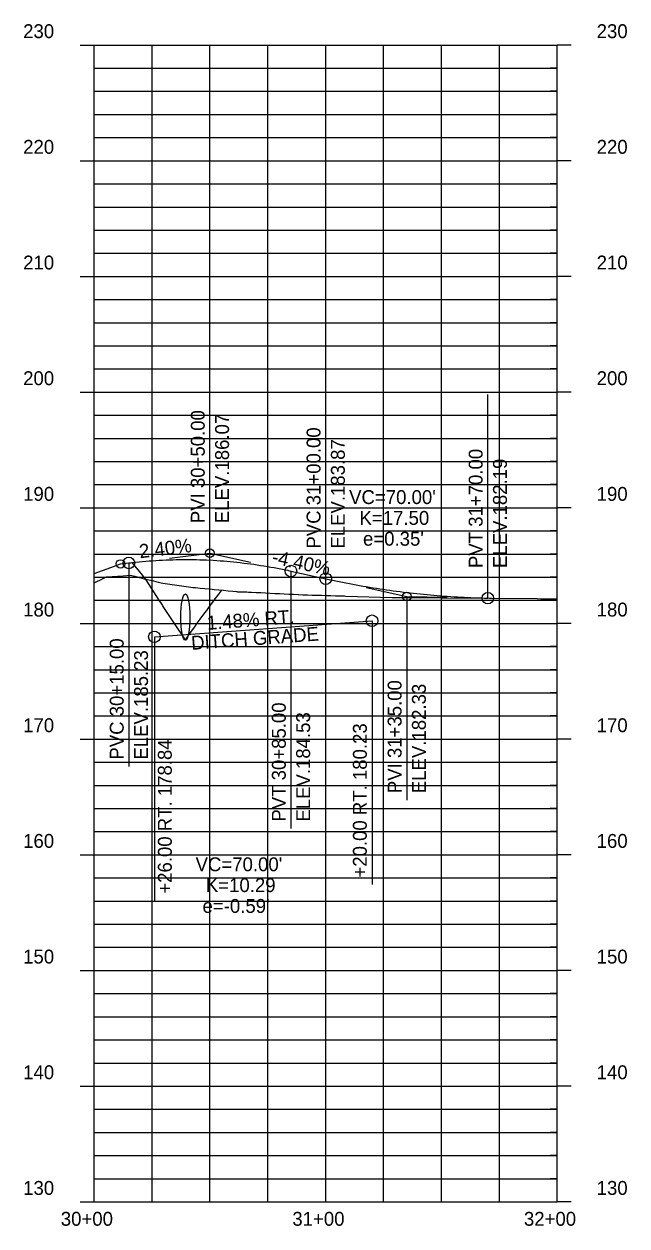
# Model space of a CAD drawing. Extents: x 1409239 to 1412142, y 1838831 to 1842626.
# Drawn here: x 1410908 to 1411168, y 1840947 to 1841467 of the extents above; entities that cross this region are included whole.
import ezdxf

# ---------------------------------------------------------------- set-up
doc = ezdxf.new("R2010")
doc.units = 0
for name, color, linetype in [('63', 7, 'Continuous'), ('R_Axis_Annotation', 7, 'Continuous'), ('R_Drainage', 7, 'Continuous'), ('R_Exist Surface', 7, 'Continuous'), ('R_Grid', 7, 'Continuous'), ('R_Grid Annot', 7, 'Continuous'), ('R_Grid_Minor', 7, 'Continuous'), ('R_Prop Surface', 7, 'Continuous'), ('R_Vert Alg', 7, 'Continuous'), ('R_Vert Alg Annot', 7, 'Continuous')]:
    doc.layers.add(name, color=color, linetype=linetype)

msp = doc.modelspace()

# ---------------------------------------------------------------- linework, layer by layer
at = {"layer": 'R_Drainage'}
msp.add_ellipse((1410977.35, 1841210.43), major_axis=(0, 10), ratio=0.2, dxfattribs=at)
at = {"layer": 'R_Exist Surface'}
msp.add_lwpolyline([(1410937.97, 1841225.2), (1410941.93, 1841227.07), (1410943.27, 1841227.75), (1410950.48, 1841228.29), (1410953.54, 1841228.59), (1410955.53, 1841228.06), (1410957.55, 1841227.52), (1410959.56, 1841226.98), (1410960.12, 1841226.84), (1410961.58, 1841226.5), (1410963.6, 1841226.04), (1410965.61, 1841225.57), (1410967.61, 1841225.11), (1410967.63, 1841225.11), (1410969.65, 1841224.81), (1410971.66, 1841224.52), (1410973.68, 1841224.23), (1410975.7, 1841223.94), (1410977.71, 1841223.66), (1410979.73, 1841223.38), (1410980.6, 1841223.26), (1410981.74, 1841223.15), (1410983.76, 1841222.97), (1410985.78, 1841222.79), (1410987.79, 1841222.62), (1410988.14, 1841222.59), (1410989.81, 1841222.41), (1410991.83, 1841222.19), (1410993.84, 1841221.98), (1410995.86, 1841221.77), (1410997.87, 1841221.57), (1410999.49, 1841221.41), (1410999.53, 1841221.41), (1410999.89, 1841221.4), (1411001.91, 1841221.34), (1411003.92, 1841221.27), (1411004.58, 1841221.25), (1411005.94, 1841221.19), (1411007.96, 1841221.09), (1411009.97, 1841220.99), (1411011.99, 1841220.88), (1411014.01, 1841220.78), (1411016.02, 1841220.67), (1411017.58, 1841220.58), (1411018.04, 1841220.56), (1411020.05, 1841220.46), (1411022.07, 1841220.36), (1411024.09, 1841220.26), (1411026.1, 1841220.16), (1411026.21, 1841220.16), (1411028.12, 1841220.03), (1411028.5, 1841220.01), (1411030.14, 1841219.97), (1411032.15, 1841219.92), (1411034.17, 1841219.88), (1411036.18, 1841219.82), (1411038.2, 1841219.77), (1411040.22, 1841219.71), (1411042.23, 1841219.65), (1411046.04, 1841219.54), (1411046.62, 1841219.52), (1411066.65, 1841218.92), (1411067.19, 1841218.91), (1411080.39, 1841218.83), (1411087.99, 1841218.76), (1411088.29, 1841218.76), (1411108.76, 1841218.58), (1411109.9, 1841218.55), (1411129.35, 1841218.38), (1411130.93, 1841218.35), (1411137.97, 1841218.29)], dxfattribs=at)
at = {"layer": 'R_Grid'}
for p, q in [((1410937.97, 1840957.67), (1410937.97, 1841457.67)), ((1410937.97, 1841457.67), (1411137.97, 1841457.67)), ((1410937.97, 1841457.67), (1411137.97, 1841457.67)), ((1411037.97, 1840957.67), (1411037.97, 1841457.67)), ((1411137.97, 1840957.67), (1411137.97, 1841457.67)), ((1410937.97, 1841407.67), (1411137.97, 1841407.67)), ((1410937.97, 1841357.67), (1411137.97, 1841357.67)), ((1410937.97, 1841307.67), (1411137.97, 1841307.67)), ((1410937.97, 1841257.67), (1411137.97, 1841257.67)), ((1410937.97, 1841207.67), (1411137.97, 1841207.67)), ((1410937.97, 1841157.67), (1411137.97, 1841157.67)), ((1410937.97, 1841107.67), (1411137.97, 1841107.67)), ((1410937.97, 1841057.67), (1411137.97, 1841057.67)), ((1410937.97, 1841007.67), (1411137.97, 1841007.67)), ((1410937.97, 1840957.67), (1411137.97, 1840957.67))]:
    msp.add_line(p, q, dxfattribs=at)
at = {"layer": 'R_Grid Annot'}
for p, q in [((1410931.97, 1841457.67), (1410937.97, 1841457.67)), ((1410931.97, 1841457.67), (1410937.97, 1841457.67)), ((1411143.97, 1841457.67), (1411137.97, 1841457.67)), ((1411143.97, 1841457.67), (1411137.97, 1841457.67)), ((1410937.97, 1841447.67), (1410940.97, 1841447.67)), ((1411137.97, 1841447.67), (1411134.97, 1841447.67)), ((1410937.97, 1841437.67), (1410940.97, 1841437.67)), ((1411137.97, 1841437.67), (1411134.97, 1841437.67)), ((1410937.97, 1841427.67), (1410940.97, 1841427.67)), ((1411137.97, 1841427.67), (1411134.97, 1841427.67)), ((1410937.97, 1841417.67), (1410940.97, 1841417.67)), ((1411137.97, 1841417.67), (1411134.97, 1841417.67)), ((1410931.97, 1841407.67), (1410937.97, 1841407.67)), ((1411143.97, 1841407.67), (1411137.97, 1841407.67)), ((1410937.97, 1841397.67), (1410940.97, 1841397.67)), ((1411137.97, 1841397.67), (1411134.97, 1841397.67)), ((1410937.97, 1841387.67), (1410940.97, 1841387.67)), ((1411137.97, 1841387.67), (1411134.97, 1841387.67)), ((1410937.97, 1841377.67), (1410940.97, 1841377.67)), ((1411137.97, 1841377.67), (1411134.97, 1841377.67)), ((1410937.97, 1841367.67), (1410940.97, 1841367.67)), ((1411137.97, 1841367.67), (1411134.97, 1841367.67)), ((1410931.97, 1841357.67), (1410937.97, 1841357.67)), ((1411143.97, 1841357.67), (1411137.97, 1841357.67)), ((1410937.97, 1841347.67), (1410940.97, 1841347.67)), ((1411137.97, 1841347.67), (1411134.97, 1841347.67)), ((1410937.97, 1841337.67), (1410940.97, 1841337.67)), ((1411137.97, 1841337.67), (1411134.97, 1841337.67)), ((1410937.97, 1841327.67), (1410940.97, 1841327.67)), ((1411137.97, 1841327.67), (1411134.97, 1841327.67)), ((1410937.97, 1841317.67), (1410940.97, 1841317.67)), ((1411137.97, 1841317.67), (1411134.97, 1841317.67)), ((1410931.97, 1841307.67), (1410937.97, 1841307.67)), ((1411143.97, 1841307.67), (1411137.97, 1841307.67)), ((1410937.97, 1841297.67), (1410940.97, 1841297.67)), ((1411137.97, 1841297.67), (1411134.97, 1841297.67)), ((1410937.97, 1841287.67), (1410940.97, 1841287.67)), ((1411137.97, 1841287.67), (1411134.97, 1841287.67)), ((1410937.97, 1841277.67), (1410940.97, 1841277.67)), ((1411137.97, 1841277.67), (1411134.97, 1841277.67)), ((1410937.97, 1841267.67), (1410940.97, 1841267.67)), ((1411137.97, 1841267.67), (1411134.97, 1841267.67)), ((1410931.97, 1841257.67), (1410937.97, 1841257.67)), ((1411143.97, 1841257.67), (1411137.97, 1841257.67)), ((1410937.97, 1841247.67), (1410940.97, 1841247.67)), ((1411137.97, 1841247.67), (1411134.97, 1841247.67)), ((1410937.97, 1841237.67), (1410940.97, 1841237.67)), ((1411137.97, 1841237.67), (1411134.97, 1841237.67)), ((1410937.97, 1841227.67), (1410940.97, 1841227.67)), ((1411137.97, 1841227.67), (1411134.97, 1841227.67)), ((1410937.97, 1841217.67), (1410940.97, 1841217.67)), ((1411137.97, 1841217.67), (1411134.97, 1841217.67)), ((1410931.97, 1841207.67), (1410937.97, 1841207.67)), ((1411143.97, 1841207.67), (1411137.97, 1841207.67)), ((1410937.97, 1841197.67), (1410940.97, 1841197.67)), ((1411137.97, 1841197.67), (1411134.97, 1841197.67)), ((1410937.97, 1841187.67), (1410940.97, 1841187.67)), ((1411137.97, 1841187.67), (1411134.97, 1841187.67)), ((1410937.97, 1841177.67), (1410940.97, 1841177.67)), ((1411137.97, 1841177.67), (1411134.97, 1841177.67)), ((1410937.97, 1841167.67), (1410940.97, 1841167.67)), ((1411137.97, 1841167.67), (1411134.97, 1841167.67)), ((1410931.97, 1841157.67), (1410937.97, 1841157.67)), ((1411143.97, 1841157.67), (1411137.97, 1841157.67)), ((1410937.97, 1841147.67), (1410940.97, 1841147.67)), ((1411137.97, 1841147.67), (1411134.97, 1841147.67)), ((1410937.97, 1841137.67), (1410940.97, 1841137.67)), ((1411137.97, 1841137.67), (1411134.97, 1841137.67)), ((1410937.97, 1841127.67), (1410940.97, 1841127.67)), ((1411137.97, 1841127.67), (1411134.97, 1841127.67)), ((1410937.97, 1841117.67), (1410940.97, 1841117.67)), ((1411137.97, 1841117.67), (1411134.97, 1841117.67)), ((1410931.97, 1841107.67), (1410937.97, 1841107.67)), ((1411143.97, 1841107.67), (1411137.97, 1841107.67)), ((1410937.97, 1841097.67), (1410940.97, 1841097.67)), ((1411137.97, 1841097.67), (1411134.97, 1841097.67)), ((1410937.97, 1841087.67), (1410940.97, 1841087.67)), ((1411137.97, 1841087.67), (1411134.97, 1841087.67)), ((1410937.97, 1841077.67), (1410940.97, 1841077.67)), ((1411137.97, 1841077.67), (1411134.97, 1841077.67)), ((1410937.97, 1841067.67), (1410940.97, 1841067.67)), ((1411137.97, 1841067.67), (1411134.97, 1841067.67)), ((1410931.97, 1841057.67), (1410937.97, 1841057.67)), ((1411143.97, 1841057.67), (1411137.97, 1841057.67)), ((1410937.97, 1841047.67), (1410940.97, 1841047.67)), ((1411137.97, 1841047.67), (1411134.97, 1841047.67)), ((1410937.97, 1841037.67), (1410940.97, 1841037.67)), ((1411137.97, 1841037.67), (1411134.97, 1841037.67)), ((1410937.97, 1841027.67), (1410940.97, 1841027.67)), ((1411137.97, 1841027.67), (1411134.97, 1841027.67)), ((1410937.97, 1841017.67), (1410940.97, 1841017.67)), ((1411137.97, 1841017.67), (1411134.97, 1841017.67)), ((1410931.97, 1841007.67), (1410937.97, 1841007.67)), ((1411143.97, 1841007.67), (1411137.97, 1841007.67)), ((1410937.97, 1840997.67), (1410940.97, 1840997.67)), ((1411137.97, 1840997.67), (1411134.97, 1840997.67)), ((1410937.97, 1840987.67), (1410940.97, 1840987.67)), ((1411137.97, 1840987.67), (1411134.97, 1840987.67)), ((1410937.97, 1840977.67), (1410940.97, 1840977.67)), ((1411137.97, 1840977.67), (1411134.97, 1840977.67)), ((1410937.97, 1840967.67), (1410940.97, 1840967.67)), ((1411137.97, 1840967.67), (1411134.97, 1840967.67)), ((1410931.97, 1840957.67), (1410937.97, 1840957.67)), ((1411143.97, 1840957.67), (1411137.97, 1840957.67))]:
    msp.add_line(p, q, dxfattribs=at)
at = {"layer": 'R_Grid_Minor'}
for p, q in [((1410962.97, 1840957.67), (1410962.97, 1841457.67)), ((1410987.97, 1840957.67), (1410987.97, 1841457.67)), ((1411012.97, 1840957.67), (1411012.97, 1841457.67)), ((1411062.97, 1840957.67), (1411062.97, 1841457.67)), ((1411087.97, 1840957.67), (1411087.97, 1841457.67)), ((1411112.97, 1840957.67), (1411112.97, 1841457.67)), ((1410937.97, 1841447.67), (1411137.97, 1841447.67)), ((1410937.97, 1841437.67), (1411137.97, 1841437.67)), ((1410937.97, 1841427.67), (1411137.97, 1841427.67)), ((1410937.97, 1841417.67), (1411137.97, 1841417.67)), ((1410937.97, 1841397.67), (1411137.97, 1841397.67)), ((1410937.97, 1841387.67), (1411137.97, 1841387.67)), ((1410937.97, 1841377.67), (1411137.97, 1841377.67)), ((1410937.97, 1841367.67), (1411137.97, 1841367.67)), ((1410937.97, 1841347.67), (1411137.97, 1841347.67)), ((1410937.97, 1841337.67), (1411137.97, 1841337.67)), ((1410937.97, 1841327.67), (1411137.97, 1841327.67)), ((1410937.97, 1841317.67), (1411137.97, 1841317.67)), ((1410937.97, 1841297.67), (1411137.97, 1841297.67)), ((1410937.97, 1841287.67), (1411137.97, 1841287.67)), ((1410937.97, 1841277.67), (1411137.97, 1841277.67)), ((1410937.97, 1841267.67), (1411137.97, 1841267.67)), ((1410937.97, 1841247.67), (1411137.97, 1841247.67)), ((1410937.97, 1841237.67), (1411137.97, 1841237.67)), ((1410937.97, 1841227.67), (1411137.97, 1841227.67)), ((1410937.97, 1841217.67), (1411137.97, 1841217.67)), ((1410937.97, 1841197.67), (1411137.97, 1841197.67)), ((1410937.97, 1841187.67), (1411137.97, 1841187.67)), ((1410937.97, 1841177.67), (1411137.97, 1841177.67)), ((1410937.97, 1841167.67), (1411137.97, 1841167.67)), ((1410937.97, 1841147.67), (1411137.97, 1841147.67)), ((1410937.97, 1841137.67), (1411137.97, 1841137.67)), ((1410937.97, 1841127.67), (1411137.97, 1841127.67)), ((1410937.97, 1841117.67), (1411137.97, 1841117.67)), ((1410937.97, 1841097.67), (1411137.97, 1841097.67)), ((1410937.97, 1841087.67), (1411137.97, 1841087.67)), ((1410937.97, 1841077.67), (1411137.97, 1841077.67)), ((1410937.97, 1841067.67), (1411137.97, 1841067.67)), ((1410937.97, 1841047.67), (1411137.97, 1841047.67)), ((1410937.97, 1841037.67), (1411137.97, 1841037.67)), ((1410937.97, 1841027.67), (1411137.97, 1841027.67)), ((1410937.97, 1841017.67), (1411137.97, 1841017.67)), ((1410937.97, 1840997.67), (1411137.97, 1840997.67)), ((1410937.97, 1840987.67), (1411137.97, 1840987.67)), ((1410937.97, 1840977.67), (1411137.97, 1840977.67)), ((1410937.97, 1840967.67), (1411137.97, 1840967.67))]:
    msp.add_line(p, q, dxfattribs=at)
at = {"layer": 'R_Prop Surface'}
for points in [[(1410937.97, 1841229.32), (1410945.12, 1841231.88), (1410949.33, 1841233.37), (1410952.97, 1841233.81), (1410953.7, 1841233.9)], [(1410953.7, 1841233.9), (1410954.21, 1841233.96), (1410955.53, 1841232.38), (1410957.55, 1841229.98), (1410958.27, 1841229.13), (1410959.34, 1841227.86), (1410959.56, 1841227.59), (1410959.68, 1841227.45), (1410961.58, 1841224.46), (1410963.6, 1841221.3), (1410965.61, 1841218.17), (1410967.43, 1841215.37), (1410967.63, 1841215.06), (1410969.65, 1841211.98), (1410971.66, 1841208.92), (1410973.68, 1841205.89), (1410974.24, 1841205.06), (1410975.5, 1841203.18), (1410975.7, 1841202.88), (1410977.35, 1841200.43), (1410977.71, 1841200.96), (1410979.73, 1841203.83), (1410981.74, 1841206.67), (1410982.51, 1841207.74), (1410983.76, 1841209.47), (1410985.78, 1841212.25), (1410986.58, 1841213.33), (1410987.79, 1841214.99), (1410989.16, 1841216.82), (1410989.81, 1841217.7), (1410991.83, 1841220.38), (1410993.11, 1841222.06)]]:
    msp.add_lwpolyline(points, dxfattribs=at)
at = {"layer": 'R_Vert Alg'}
for p, q in [((1410949.35, 1841233.38), (1410952.97, 1841233.81)), ((1411022.97, 1841230.31), (1411037.97, 1841227.01)), ((1410963.97, 1841201.86), (1411057.97, 1841208.82))]:
    msp.add_line(p, q, dxfattribs=at)
for points in [[(1410952.97, 1841233.81), (1410954.43, 1841233.98), (1410955.89, 1841234.14), (1410957.34, 1841234.29), (1410958.8, 1841234.43), (1410960.26, 1841234.56), (1410961.72, 1841234.68), (1410963.18, 1841234.78), (1410964.64, 1841234.88), (1410966.09, 1841234.97), (1410967.55, 1841235.05), (1410969.01, 1841235.11), (1410970.47, 1841235.17), (1410971.93, 1841235.21), (1410973.39, 1841235.25), (1410974.84, 1841235.27), (1410976.3, 1841235.29), (1410977.76, 1841235.29), (1410979.22, 1841235.29), (1410980.68, 1841235.27), (1410982.14, 1841235.25), (1410983.59, 1841235.21), (1410985.05, 1841235.16), (1410986.51, 1841235.1), (1410989.43, 1841234.96), (1410990.89, 1841234.87), (1410992.34, 1841234.77), (1410993.8, 1841234.66), (1410995.26, 1841234.54), (1410996.72, 1841234.41), (1410998.18, 1841234.27), (1410999.64, 1841234.12), (1411001.09, 1841233.96), (1411002.55, 1841233.79), (1411004.01, 1841233.61), (1411005.47, 1841233.42), (1411006.93, 1841233.22), (1411008.39, 1841233), (1411009.84, 1841232.78), (1411011.3, 1841232.55), (1411012.76, 1841232.3), (1411014.22, 1841232.05), (1411015.68, 1841231.79), (1411017.14, 1841231.51), (1411018.59, 1841231.23), (1411020.05, 1841230.93), (1411021.51, 1841230.63), (1411022.97, 1841230.31)], [(1411037.97, 1841227.01), (1411039.43, 1841226.69), (1411040.89, 1841226.38), (1411042.34, 1841226.08), (1411043.8, 1841225.78), (1411045.26, 1841225.48), (1411046.72, 1841225.2), (1411048.18, 1841224.92), (1411049.64, 1841224.64), (1411051.09, 1841224.37), (1411052.55, 1841224.11), (1411054.01, 1841223.85), (1411055.47, 1841223.6), (1411056.93, 1841223.35), (1411058.39, 1841223.12), (1411059.84, 1841222.88), (1411061.3, 1841222.66), (1411062.76, 1841222.44), (1411064.22, 1841222.22), (1411065.68, 1841222.01), (1411067.14, 1841221.81), (1411068.59, 1841221.61), (1411070.05, 1841221.42), (1411071.51, 1841221.24), (1411074.43, 1841220.89), (1411075.89, 1841220.72), (1411077.34, 1841220.56), (1411078.8, 1841220.41), (1411080.26, 1841220.26), (1411081.72, 1841220.12), (1411083.18, 1841219.99), (1411084.64, 1841219.86), (1411086.09, 1841219.73), (1411087.55, 1841219.62), (1411089.01, 1841219.5), (1411090.47, 1841219.4), (1411091.93, 1841219.3), (1411093.39, 1841219.21), (1411094.84, 1841219.12), (1411096.3, 1841219.04), (1411097.76, 1841218.97), (1411099.22, 1841218.9), (1411100.68, 1841218.83), (1411102.14, 1841218.78), (1411103.59, 1841218.73), (1411105.05, 1841218.68), (1411106.51, 1841218.64), (1411107.97, 1841218.61)]]:
    msp.add_lwpolyline(points, dxfattribs=at)
at = {"layer": 'R_Vert Alg Annot'}
for p, q in [((1410987.97, 1841248.01), (1410987.97, 1841326.01)), ((1411037.97, 1841237.01), (1411037.97, 1841315.01)), ((1411107.97, 1841228.61), (1411107.97, 1841306.61)), ((1410987.97, 1841238.01), (1410987.97, 1841248.01)), ((1410970.47, 1841235.91), (1410987.97, 1841238.01)), ((1410987.97, 1841238.01), (1411005.47, 1841234.16)), ((1411037.97, 1841227.01), (1411037.97, 1841237.01)), ((1410952.97, 1841233.81), (1410952.97, 1841223.81)), ((1411022.97, 1841230.31), (1411022.97, 1841197.01)), ((1411107.97, 1841218.61), (1411107.97, 1841228.61)), ((1410952.97, 1841223.81), (1410952.97, 1841145.81)), ((1411055.47, 1841223.16), (1411072.97, 1841219.31)), ((1411072.97, 1841219.31), (1411090.47, 1841218.96)), ((1411072.97, 1841219.31), (1411072.97, 1841209.31)), ((1411057.97, 1841208.82), (1411057.97, 1841178.82)), ((1411072.97, 1841209.31), (1411072.97, 1841131.31)), ((1410963.97, 1841201.86), (1410963.97, 1841171.86)), ((1411022.97, 1841197.01), (1411022.97, 1841119.01)), ((1411057.97, 1841178.82), (1411057.97, 1841094.82)), ((1410963.97, 1841171.86), (1410963.97, 1841087.86))]:
    msp.add_line(p, q, dxfattribs=at)
for centre, radius in [((1410987.97, 1841238.01), 1.85), ((1410949.35, 1841233.38), 1.85), ((1410952.97, 1841233.81), 2.5), ((1411022.97, 1841230.31), 2.5), ((1411037.97, 1841227.01), 2.5), ((1411072.97, 1841219.31), 1.85), ((1411107.97, 1841218.61), 2.5), ((1411057.97, 1841208.82), 2.5), ((1410963.97, 1841201.86), 2.5)]:
    msp.add_circle(centre, radius, dxfattribs=at)

# ---------------------------------------------------------------- texts
at = {"layer": '63'}
msp.add_text('-', height=0.0001, dxfattribs=at).set_placement((1410937.97, 1840957.67))
at = {"layer": 'R_Axis_Annotation'}
for s, p in [('230', (1410907.3, 1841460.67)), ('230', (1410907.3, 1841460.67)), ('230', (1411154.98, 1841460.67)), ('230', (1411154.98, 1841460.67)), ('220', (1410907.3, 1841410.67)), ('220', (1411154.98, 1841410.67)), ('210', (1410907.3, 1841360.67)), ('210', (1411154.98, 1841360.67)), ('200', (1410907.3, 1841310.67)), ('200', (1411154.98, 1841310.67)), ('190', (1410907.3, 1841260.67)), ('190', (1411154.98, 1841260.67)), ('180', (1410907.3, 1841210.67)), ('180', (1411154.98, 1841210.67)), ('170', (1410907.3, 1841160.67)), ('170', (1411154.98, 1841160.67)), ('160', (1410907.3, 1841110.67)), ('160', (1411154.98, 1841110.67)), ('150', (1410907.3, 1841060.67)), ('150', (1411154.98, 1841060.67)), ('140', (1410907.3, 1841010.67)), ('140', (1411154.98, 1841010.67)), ('130', (1410907.3, 1840960.67)), ('130', (1411154.98, 1840960.67)), ('30+00', (1410923.56, 1840947.32)), ('31+00', (1411023.56, 1840947.32)), ('32+00', (1411123.56, 1840947.32))]:
    msp.add_text(s, height=6, dxfattribs=at).set_placement(p)
at = {"layer": 'R_Vert Alg Annot'}
for s, rotation, p in [('PVI 30+50.00', 90, (1410985.72, 1841251.01)), ('ELEV.186.07', 90, (1410996.22, 1841251.01)), ('PVC 31+00.00', 90, (1411035.72, 1841240.01)), ('ELEV.183.87', 90, (1411046.22, 1841240.01)), ('PVT 31+70.00', 90, (1411105.72, 1841231.61)), ('ELEV.182.19', 90, (1411116.22, 1841231.61)), ('2.40%', 6.8428, (1410957.76, 1841235.82)), ('-4.40%', 347.5926, (1411014.38, 1841233.74)), ('1.48% RT. ', 4.2322, (1410986.84, 1841204.87)), ('DITCH GRADE', 4.2322, (1410980.08, 1841196.22)), ('PVC 30+15.00', 90, (1410950.72, 1841148.81)), ('ELEV.185.23', 90, (1410961.22, 1841148.81)), ('PVI 31+35.00', 90, (1411070.72, 1841134.31)), ('ELEV.182.33', 90, (1411081.22, 1841134.31)), ('PVT 30+85.00', 90, (1411020.72, 1841122.01)), ('ELEV.184.53', 90, (1411031.22, 1841122.01)), ('+20.00 RT. 180.23', 90, (1411055.72, 1841097.82)), ('+26.00 RT. 178.84', 90, (1410971.49, 1841090.86))]:
    msp.add_text(s, height=6, rotation=rotation, dxfattribs=at).set_placement(p)
for s, p in [("VC=70.00'", (1411048.07, 1841259.28)), ('K=17.50', (1411052.56, 1841250.28)), ("e=0.35'", (1411054.07, 1841241.28)), ("VC=70.00'", (1410981.77, 1841100.56)), ('K=10.29', (1410986.2, 1841091.56)), ("e=-0.59'", (1410984.77, 1841082.56))]:
    msp.add_text(s, height=6, dxfattribs=at).set_placement(p)

doc.saveas('drawing.dxf')
